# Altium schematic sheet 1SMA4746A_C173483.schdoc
size 127 x 101 mm
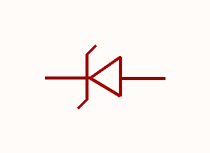
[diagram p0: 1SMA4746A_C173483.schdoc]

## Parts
D?  1sma4746a_c173483  [SMA_L4.4-W2.6-LS5.0-RD]  (value not drawn)

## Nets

Not connected (* = marked no-connect by the designer): D? 1(K) 2(A)

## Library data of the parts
D? = 1sma4746a_c173483: 二极管配置:1个独立式;稳压值(标称值):18V;稳压值(范围值):16.8V~19.2V;耗散功率(Pd):1W;; Manufacturer: MDD(辰达半导体); AddInBom: yes; ModelId: a2d22152f8d5421c8e96dbd56af7c345; ModelTransform: 204.724,98.425,0,0,0,0,0,0,0; Diode Configuration: 1个独立式; Zener Voltage(Nom): 18V; Reverse Leakage Current (Ir): 5uA@13V; Pd - Power Dissipation: 1W; Impedance(Zzt): 20Ω; Operating Junction Temperature Range: -55℃~+150℃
